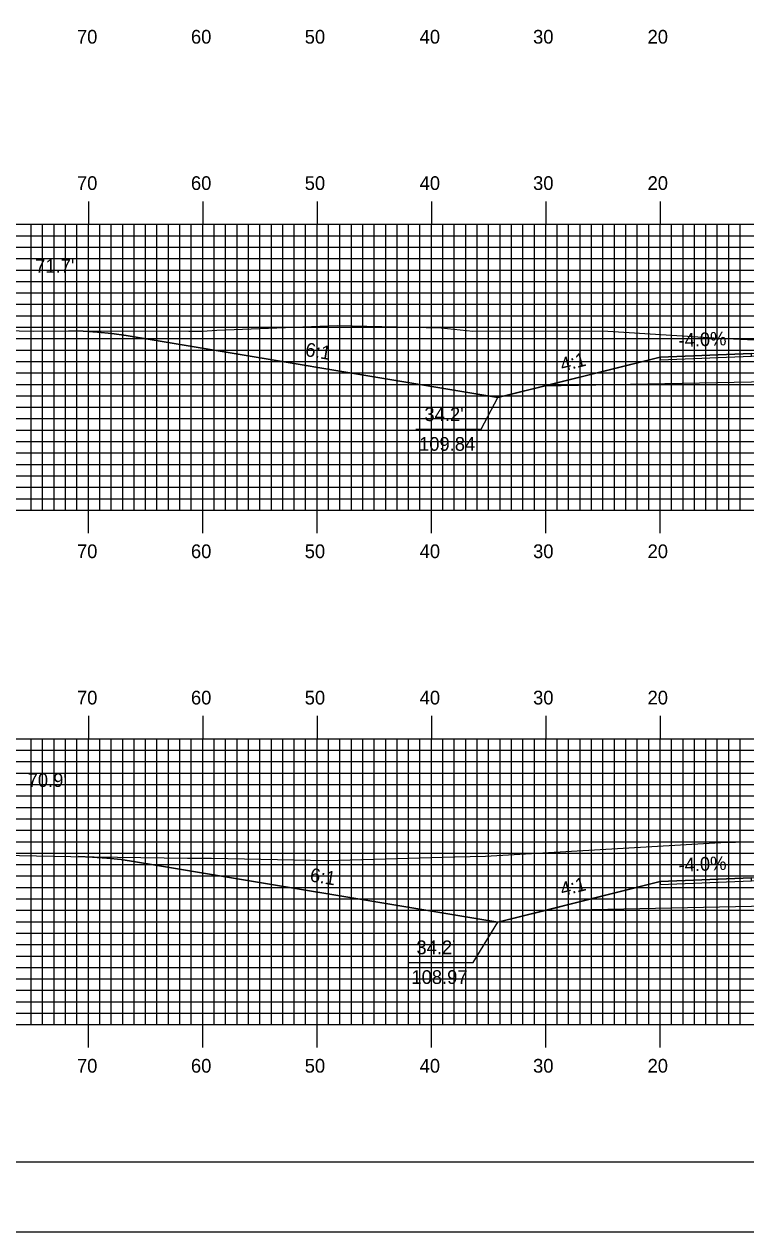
# Model space of a CAD drawing. Extents: x 1779893 to 1780236, y 442591 to 442811.
# Drawn here: x 1779982.7 to 1780045.9, y 442590.5 to 442696.2 of the extents above; entities that cross this region are included whole.
import ezdxf

# ---------------------------------------------------------------- set-up
doc = ezdxf.new("R2010")
doc.units = 0
for name, color, linetype in [('ANNOTATION', 7, 'Continuous'), ('BORDER', 7, 'Continuous'), ('D_Roadway_Centerline', 7, 'Continuous'), ('D_Roadway_Edge_Shoulder', 7, 'Continuous'), ('D_Roadway_SlopeLines', 7, 'Continuous'), ('D_Roadway_SubGrade', 7, 'Continuous'), ('D_Text_Standard', 7, 'Continuous'), ('H_V ANNOTATION', 7, 'Continuous'), ('MAJOR', 7, 'Continuous'), ('MINOR', 7, 'Continuous'), ('PLOT BOUNDARY', 7, 'Continuous'), ('S_Roadway_Centerline', 7, 'Continuous')]:
    doc.layers.add(name, color=color, linetype=linetype)

msp = doc.modelspace()

# ---------------------------------------------------------------- linework, layer by layer
at = {"layer": 'ANNOTATION'}
for points in [[(1780017.01, 442660.74), (1780022.7, 442660.74), (1780024.18, 442663.51)], [(1780016.31, 442614.11), (1780022.01, 442614.11), (1780024.18, 442617.63)]]:
    msp.add_lwpolyline(points, dxfattribs=at)
at = {"layer": 'BORDER'}
msp.add_lwpolyline([(1779908.76, 442596.67), (1780228.76, 442596.67), (1780228.76, 442806.67), (1779908.76, 442806.67)], close=True, dxfattribs=at)
at = {"layer": 'D_Roadway_Centerline'}
for points in [[(1779986.66, 442669.34), (1779987.91, 442669.32), (1779989.16, 442669.24), (1779990.41, 442669.11), (1779991.66, 442668.93), (1780024.18, 442663.51), (1780028.18, 442664.51), (1780038.36, 442667.05), (1780046.36, 442667.37), (1780058.36, 442667.61), (1780070.36, 442667.37), (1780078.36, 442667.05), (1780088.53, 442664.51), (1780092.53, 442663.51), (1780103.56, 442665.35), (1780104.81, 442665.52), (1780106.06, 442665.64), (1780107.31, 442665.68), (1780108.56, 442665.67)], [(1779987.48, 442623.37), (1779988.73, 442623.33), (1779989.98, 442623.24), (1779991.23, 442623.1), (1779992.48, 442622.92), (1780024.18, 442617.63), (1780028.18, 442618.63), (1780038.36, 442621.18), (1780046.36, 442621.5), (1780058.36, 442621.74), (1780070.36, 442621.5), (1780078.36, 442621.18), (1780088.53, 442618.63), (1780092.53, 442617.63), (1780110.57, 442620.64), (1780111.82, 442620.81), (1780113.07, 442620.89), (1780114.32, 442620.88), (1780115.57, 442620.79)]]:
    msp.add_lwpolyline(points, dxfattribs=at)
at = {"layer": 'D_Roadway_Edge_Shoulder'}
for points in [[(1780046.36, 442667.37), (1780038.36, 442667.05), (1780038.36, 442666.8), (1780046.36, 442667.12)], [(1780046.36, 442621.5), (1780038.36, 442621.18), (1780038.36, 442620.93), (1780046.36, 442621.25)]]:
    msp.add_lwpolyline(points, close=True, dxfattribs=at)
at = {"layer": 'D_Roadway_SlopeLines'}
for points in [[(1780024.18, 442663.51), (1779991.66, 442668.93), (1779990.41, 442669.11), (1779989.16, 442669.24), (1779987.91, 442669.32), (1779986.66, 442669.34)], [(1780038.36, 442667.05), (1780024.18, 442663.51)], [(1780024.18, 442617.63), (1779992.48, 442622.92), (1779991.23, 442623.1), (1779989.98, 442623.24), (1779988.73, 442623.33), (1779987.48, 442623.37)], [(1780038.36, 442621.18), (1780024.18, 442617.63)]]:
    msp.add_lwpolyline(points, dxfattribs=at)
at = {"layer": 'D_Roadway_SubGrade'}
for points in [[(1780046.36, 442664.87), (1780028.18, 442664.51), (1780038.36, 442667.05), (1780038.36, 442666.8), (1780046.36, 442667.12), (1780058.36, 442667.36), (1780070.36, 442667.12), (1780078.36, 442666.8), (1780078.36, 442667.05), (1780088.53, 442664.51), (1780070.36, 442664.87), (1780058.36, 442665.11)], [(1780046.36, 442619), (1780028.18, 442618.63), (1780038.36, 442621.18), (1780038.36, 442620.93), (1780046.36, 442621.25), (1780058.36, 442621.49), (1780070.36, 442621.25), (1780078.36, 442620.93), (1780078.36, 442621.18), (1780088.53, 442618.63), (1780070.36, 442619), (1780058.36, 442619.24)]]:
    msp.add_lwpolyline(points, close=True, dxfattribs=at)
at = {"layer": 'MAJOR'}
for p, q in [((1779988.36, 442680.67), (1779988.36, 442678.67)), ((1779998.36, 442680.67), (1779998.36, 442678.67)), ((1780008.36, 442680.67), (1780008.36, 442678.67)), ((1780018.36, 442680.67), (1780018.36, 442678.67)), ((1780028.36, 442680.67), (1780028.36, 442678.67)), ((1780038.36, 442680.67), (1780038.36, 442678.67)), ((1779918.36, 442678.67), (1780198.36, 442678.67)), ((1779918.36, 442678.67), (1780198.36, 442678.67)), ((1779988.36, 442653.67), (1779988.36, 442678.67)), ((1779998.36, 442653.67), (1779998.36, 442678.67)), ((1780008.36, 442653.67), (1780008.36, 442678.67)), ((1780018.36, 442653.67), (1780018.36, 442678.67)), ((1780028.36, 442653.67), (1780028.36, 442678.67)), ((1780038.36, 442653.67), (1780038.36, 442678.67)), ((1779918.36, 442673.67), (1780198.36, 442673.67)), ((1779918.36, 442668.67), (1780198.36, 442668.67)), ((1779918.36, 442663.67), (1780198.36, 442663.67)), ((1779918.36, 442658.67), (1780198.36, 442658.67)), ((1779918.36, 442653.67), (1780198.36, 442653.67)), ((1779918.36, 442653.67), (1780198.36, 442653.67)), ((1779988.36, 442651.66), (1779988.36, 442653.67)), ((1779998.36, 442651.66), (1779998.36, 442653.67)), ((1780008.36, 442651.66), (1780008.36, 442653.67)), ((1780018.36, 442651.66), (1780018.36, 442653.67)), ((1780028.36, 442651.66), (1780028.36, 442653.67)), ((1780038.36, 442651.66), (1780038.36, 442653.67)), ((1779988.36, 442635.67), (1779988.36, 442633.67)), ((1779998.36, 442635.67), (1779998.36, 442633.67)), ((1780008.36, 442635.67), (1780008.36, 442633.67)), ((1780018.36, 442635.67), (1780018.36, 442633.67)), ((1780028.36, 442635.67), (1780028.36, 442633.67)), ((1780038.36, 442635.67), (1780038.36, 442633.67)), ((1779918.36, 442633.67), (1780198.36, 442633.67)), ((1779918.36, 442633.67), (1780198.36, 442633.67)), ((1779988.36, 442608.67), (1779988.36, 442633.67)), ((1779998.36, 442608.67), (1779998.36, 442633.67)), ((1780008.36, 442608.67), (1780008.36, 442633.67)), ((1780018.36, 442608.67), (1780018.36, 442633.67)), ((1780028.36, 442608.67), (1780028.36, 442633.67)), ((1780038.36, 442608.67), (1780038.36, 442633.67)), ((1779918.36, 442628.67), (1780198.36, 442628.67)), ((1779918.36, 442623.67), (1780198.36, 442623.67)), ((1779918.36, 442618.67), (1780198.36, 442618.67)), ((1779918.36, 442613.67), (1780198.36, 442613.67)), ((1779918.36, 442608.67), (1780198.36, 442608.67)), ((1779918.36, 442608.67), (1780198.36, 442608.67)), ((1779988.36, 442606.66), (1779988.36, 442608.67)), ((1779998.36, 442606.66), (1779998.36, 442608.67)), ((1780008.36, 442606.66), (1780008.36, 442608.67)), ((1780018.36, 442606.66), (1780018.36, 442608.67)), ((1780028.36, 442606.66), (1780028.36, 442608.67)), ((1780038.36, 442606.66), (1780038.36, 442608.67))]:
    msp.add_line(p, q, dxfattribs=at)
at = {"layer": 'MINOR'}
for p, q in [((1779983.36, 442653.67), (1779983.36, 442678.67)), ((1779984.36, 442653.67), (1779984.36, 442678.67)), ((1779985.36, 442653.67), (1779985.36, 442678.67)), ((1779986.36, 442653.67), (1779986.36, 442678.67)), ((1779987.36, 442653.67), (1779987.36, 442678.67)), ((1779989.36, 442653.67), (1779989.36, 442678.67)), ((1779990.36, 442653.67), (1779990.36, 442678.67)), ((1779991.36, 442653.67), (1779991.36, 442678.67)), ((1779992.36, 442653.67), (1779992.36, 442678.67)), ((1779993.36, 442653.67), (1779993.36, 442678.67)), ((1779994.36, 442653.67), (1779994.36, 442678.67)), ((1779995.36, 442653.67), (1779995.36, 442678.67)), ((1779996.36, 442653.67), (1779996.36, 442678.67)), ((1779997.36, 442653.67), (1779997.36, 442678.67)), ((1779999.36, 442653.67), (1779999.36, 442678.67)), ((1780000.36, 442653.67), (1780000.36, 442678.67)), ((1780001.36, 442653.67), (1780001.36, 442678.67)), ((1780002.36, 442653.67), (1780002.36, 442678.67)), ((1780003.36, 442653.67), (1780003.36, 442678.67)), ((1780004.36, 442653.67), (1780004.36, 442678.67)), ((1780005.36, 442653.67), (1780005.36, 442678.67)), ((1780006.36, 442653.67), (1780006.36, 442678.67)), ((1780007.36, 442653.67), (1780007.36, 442678.67)), ((1780009.36, 442653.67), (1780009.36, 442678.67)), ((1780010.36, 442653.67), (1780010.36, 442678.67)), ((1780011.36, 442653.67), (1780011.36, 442678.67)), ((1780012.36, 442653.67), (1780012.36, 442678.67)), ((1780013.36, 442653.67), (1780013.36, 442678.67)), ((1780014.36, 442653.67), (1780014.36, 442678.67)), ((1780015.36, 442653.67), (1780015.36, 442678.67)), ((1780016.36, 442653.67), (1780016.36, 442678.67)), ((1780017.36, 442653.67), (1780017.36, 442678.67)), ((1780019.36, 442653.67), (1780019.36, 442678.67)), ((1780020.36, 442653.67), (1780020.36, 442678.67)), ((1780021.36, 442653.67), (1780021.36, 442678.67)), ((1780022.36, 442653.67), (1780022.36, 442678.67)), ((1780023.36, 442653.67), (1780023.36, 442678.67)), ((1780024.36, 442653.67), (1780024.36, 442678.67)), ((1780025.36, 442653.67), (1780025.36, 442678.67)), ((1780026.36, 442653.67), (1780026.36, 442678.67)), ((1780027.36, 442653.67), (1780027.36, 442678.67)), ((1780029.36, 442653.67), (1780029.36, 442678.67)), ((1780030.36, 442653.67), (1780030.36, 442678.67)), ((1780031.36, 442653.67), (1780031.36, 442678.67)), ((1780032.36, 442653.67), (1780032.36, 442678.67)), ((1780033.36, 442653.67), (1780033.36, 442678.67)), ((1780034.36, 442653.67), (1780034.36, 442678.67)), ((1780035.36, 442653.67), (1780035.36, 442678.67)), ((1780036.36, 442653.67), (1780036.36, 442678.67)), ((1780037.36, 442653.67), (1780037.36, 442678.67)), ((1780039.36, 442653.67), (1780039.36, 442678.67)), ((1780040.36, 442653.67), (1780040.36, 442678.67)), ((1780041.36, 442653.67), (1780041.36, 442678.67)), ((1780042.36, 442653.67), (1780042.36, 442678.67)), ((1780043.36, 442653.67), (1780043.36, 442678.67)), ((1780044.36, 442653.67), (1780044.36, 442678.67)), ((1780045.36, 442653.67), (1780045.36, 442678.67)), ((1779918.36, 442677.67), (1780198.36, 442677.67)), ((1779918.36, 442676.67), (1780198.36, 442676.67)), ((1779918.36, 442675.67), (1780198.36, 442675.67)), ((1779918.36, 442674.67), (1780198.36, 442674.67)), ((1779918.36, 442672.67), (1780198.36, 442672.67)), ((1779918.36, 442671.67), (1780198.36, 442671.67)), ((1779918.36, 442670.67), (1780198.36, 442670.67)), ((1779918.36, 442669.67), (1780198.36, 442669.67)), ((1779918.36, 442667.67), (1780198.36, 442667.67)), ((1779918.36, 442666.67), (1780198.36, 442666.67)), ((1779918.36, 442665.67), (1780198.36, 442665.67)), ((1779918.36, 442664.67), (1780198.36, 442664.67)), ((1779918.36, 442662.67), (1780198.36, 442662.67)), ((1779918.36, 442661.67), (1780198.36, 442661.67)), ((1779918.36, 442660.67), (1780198.36, 442660.67)), ((1779918.36, 442659.67), (1780198.36, 442659.67)), ((1779918.36, 442657.67), (1780198.36, 442657.67)), ((1779918.36, 442656.67), (1780198.36, 442656.67)), ((1779918.36, 442655.67), (1780198.36, 442655.67)), ((1779918.36, 442654.67), (1780198.36, 442654.67)), ((1779983.36, 442608.67), (1779983.36, 442633.67)), ((1779984.36, 442608.67), (1779984.36, 442633.67)), ((1779985.36, 442608.67), (1779985.36, 442633.67)), ((1779986.36, 442608.67), (1779986.36, 442633.67)), ((1779987.36, 442608.67), (1779987.36, 442633.67)), ((1779989.36, 442608.67), (1779989.36, 442633.67)), ((1779990.36, 442608.67), (1779990.36, 442633.67)), ((1779991.36, 442608.67), (1779991.36, 442633.67)), ((1779992.36, 442608.67), (1779992.36, 442633.67)), ((1779993.36, 442608.67), (1779993.36, 442633.67)), ((1779994.36, 442608.67), (1779994.36, 442633.67)), ((1779995.36, 442608.67), (1779995.36, 442633.67)), ((1779996.36, 442608.67), (1779996.36, 442633.67)), ((1779997.36, 442608.67), (1779997.36, 442633.67)), ((1779999.36, 442608.67), (1779999.36, 442633.67)), ((1780000.36, 442608.67), (1780000.36, 442633.67)), ((1780001.36, 442608.67), (1780001.36, 442633.67)), ((1780002.36, 442608.67), (1780002.36, 442633.67)), ((1780003.36, 442608.67), (1780003.36, 442633.67)), ((1780004.36, 442608.67), (1780004.36, 442633.67)), ((1780005.36, 442608.67), (1780005.36, 442633.67)), ((1780006.36, 442608.67), (1780006.36, 442633.67)), ((1780007.36, 442608.67), (1780007.36, 442633.67)), ((1780009.36, 442608.67), (1780009.36, 442633.67)), ((1780010.36, 442608.67), (1780010.36, 442633.67)), ((1780011.36, 442608.67), (1780011.36, 442633.67)), ((1780012.36, 442608.67), (1780012.36, 442633.67)), ((1780013.36, 442608.67), (1780013.36, 442633.67)), ((1780014.36, 442608.67), (1780014.36, 442633.67)), ((1780015.36, 442608.67), (1780015.36, 442633.67)), ((1780016.36, 442608.67), (1780016.36, 442633.67)), ((1780017.36, 442608.67), (1780017.36, 442633.67)), ((1780019.36, 442608.67), (1780019.36, 442633.67)), ((1780020.36, 442608.67), (1780020.36, 442633.67)), ((1780021.36, 442608.67), (1780021.36, 442633.67)), ((1780022.36, 442608.67), (1780022.36, 442633.67)), ((1780023.36, 442608.67), (1780023.36, 442633.67)), ((1780024.36, 442608.67), (1780024.36, 442633.67)), ((1780025.36, 442608.67), (1780025.36, 442633.67)), ((1780026.36, 442608.67), (1780026.36, 442633.67)), ((1780027.36, 442608.67), (1780027.36, 442633.67)), ((1780029.36, 442608.67), (1780029.36, 442633.67)), ((1780030.36, 442608.67), (1780030.36, 442633.67)), ((1780031.36, 442608.67), (1780031.36, 442633.67)), ((1780032.36, 442608.67), (1780032.36, 442633.67)), ((1780033.36, 442608.67), (1780033.36, 442633.67)), ((1780034.36, 442608.67), (1780034.36, 442633.67)), ((1780035.36, 442608.67), (1780035.36, 442633.67)), ((1780036.36, 442608.67), (1780036.36, 442633.67)), ((1780037.36, 442608.67), (1780037.36, 442633.67)), ((1780039.36, 442608.67), (1780039.36, 442633.67)), ((1780040.36, 442608.67), (1780040.36, 442633.67)), ((1780041.36, 442608.67), (1780041.36, 442633.67)), ((1780042.36, 442608.67), (1780042.36, 442633.67)), ((1780043.36, 442608.67), (1780043.36, 442633.67)), ((1780044.36, 442608.67), (1780044.36, 442633.67)), ((1780045.36, 442608.67), (1780045.36, 442633.67)), ((1779918.36, 442632.67), (1780198.36, 442632.67)), ((1779918.36, 442631.67), (1780198.36, 442631.67)), ((1779918.36, 442630.67), (1780198.36, 442630.67)), ((1779918.36, 442629.67), (1780198.36, 442629.67)), ((1779918.36, 442627.67), (1780198.36, 442627.67)), ((1779918.36, 442626.67), (1780198.36, 442626.67)), ((1779918.36, 442625.67), (1780198.36, 442625.67)), ((1779918.36, 442624.67), (1780198.36, 442624.67)), ((1779918.36, 442622.67), (1780198.36, 442622.67)), ((1779918.36, 442621.67), (1780198.36, 442621.67)), ((1779918.36, 442620.67), (1780198.36, 442620.67)), ((1779918.36, 442619.67), (1780198.36, 442619.67)), ((1779918.36, 442617.67), (1780198.36, 442617.67)), ((1779918.36, 442616.67), (1780198.36, 442616.67)), ((1779918.36, 442615.67), (1780198.36, 442615.67)), ((1779918.36, 442614.67), (1780198.36, 442614.67)), ((1779918.36, 442612.67), (1780198.36, 442612.67)), ((1779918.36, 442611.67), (1780198.36, 442611.67)), ((1779918.36, 442610.67), (1780198.36, 442610.67)), ((1779918.36, 442609.67), (1780198.36, 442609.67))]:
    msp.add_line(p, q, dxfattribs=at)
at = {"layer": 'PLOT BOUNDARY'}
msp.add_lwpolyline([(1779892.57, 442590.55), (1780232.57, 442590.55), (1780232.57, 442810.55), (1779892.57, 442810.55)], close=True, dxfattribs=at)
at = {"layer": 'S_Roadway_Centerline'}
for points in [[(1779977.17, 442669.48), (1779983.58, 442669.33), (1779995.57, 442669.36), (1779997.14, 442669.33), (1779998.34, 442669.33), (1779999.6, 442669.42), (1780010.11, 442669.81), (1780019.2, 442669.6), (1780021.97, 442669.33), (1780024.59, 442669.34), (1780033.79, 442669.33), (1780043.51, 442668.72), (1780049.74, 442668.41), (1780065.11, 442667.79), (1780068.68, 442667.78), (1780072.85, 442667.59), (1780080.27, 442667.53), (1780088.09, 442666.65), (1780096.82, 442666.12), (1780110.25, 442665.6), (1780115.63, 442665.3), (1780120.75, 442665.09)], [(1779976.32, 442623.59), (1779986.82, 442623.38), (1779997.03, 442623.23), (1779999.13, 442623.22), (1780009.2, 442623.03), (1780020.4, 442623.35), (1780023.1, 442623.4), (1780042.65, 442624.54), (1780043.68, 442624.6), (1780062.86, 442625.04), (1780067.38, 442625.14), (1780067.5, 442625.13), (1780067.64, 442625.13), (1780079.11, 442624.13), (1780090.25, 442623.7), (1780092.32, 442623.47), (1780102.07, 442622.16), (1780114.01, 442620.96), (1780125.74, 442619.66)]]:
    msp.add_lwpolyline(points, dxfattribs=at)

# ---------------------------------------------------------------- texts
at = {"layer": 'ANNOTATION'}
for s, rotation, p in [('-4.0%', 2.2906, (1780039.99, 442667.92)), ('6:1', 350.5377, (1780007.26, 442667.16)), ('4:1', 14.0362, (1780029.8, 442665.78)), ('-4.0%', 2.2906, (1780039.99, 442622.04)), ('6:1', 350.5377, (1780007.67, 442621.21)), ('4:1', 14.0362, (1780029.8, 442619.9))]:
    msp.add_text(s, height=1.2, rotation=rotation, dxfattribs=at).set_placement(p)
for s, p in [("34.2'", (1780017.75, 442661.46)), ('109.84', (1780017.28, 442658.86)), ("34.2'", (1780017.05, 442614.83)), ('108.97', (1780016.61, 442612.23))]:
    msp.add_text(s, height=1.2, dxfattribs=at).set_placement(p)
at = {"layer": 'D_Text_Standard'}
for s, p in [("71.7'", (1779983.71, 442674.43)), ("70.9'", (1779983.05, 442629.46))]:
    msp.add_text(s, height=1.2, dxfattribs=at).set_placement(p)
at = {"layer": 'H_V ANNOTATION'}
for s, p in [('70', (1779987.36, 442694.47)), ('60', (1779997.33, 442694.47)), ('50', (1780007.28, 442694.47)), ('40', (1780017.33, 442694.47)), ('30', (1780027.25, 442694.47)), ('20', (1780037.26, 442694.47)), ('70', (1779987.36, 442681.67)), ('60', (1779997.33, 442681.67)), ('50', (1780007.28, 442681.67)), ('40', (1780017.33, 442681.67)), ('30', (1780027.25, 442681.67)), ('20', (1780037.26, 442681.67)), ('70', (1779987.36, 442649.47)), ('60', (1779997.33, 442649.47)), ('50', (1780007.28, 442649.47)), ('40', (1780017.33, 442649.47)), ('30', (1780027.25, 442649.47)), ('20', (1780037.26, 442649.47)), ('70', (1779987.36, 442636.67)), ('60', (1779997.33, 442636.67)), ('50', (1780007.28, 442636.67)), ('40', (1780017.33, 442636.67)), ('30', (1780027.25, 442636.67)), ('20', (1780037.26, 442636.67)), ('70', (1779987.36, 442604.47)), ('60', (1779997.33, 442604.47)), ('50', (1780007.28, 442604.47)), ('40', (1780017.33, 442604.47)), ('30', (1780027.25, 442604.47)), ('20', (1780037.26, 442604.47))]:
    msp.add_text(s, height=1.2, dxfattribs=at).set_placement(p)

doc.saveas('drawing.dxf')
